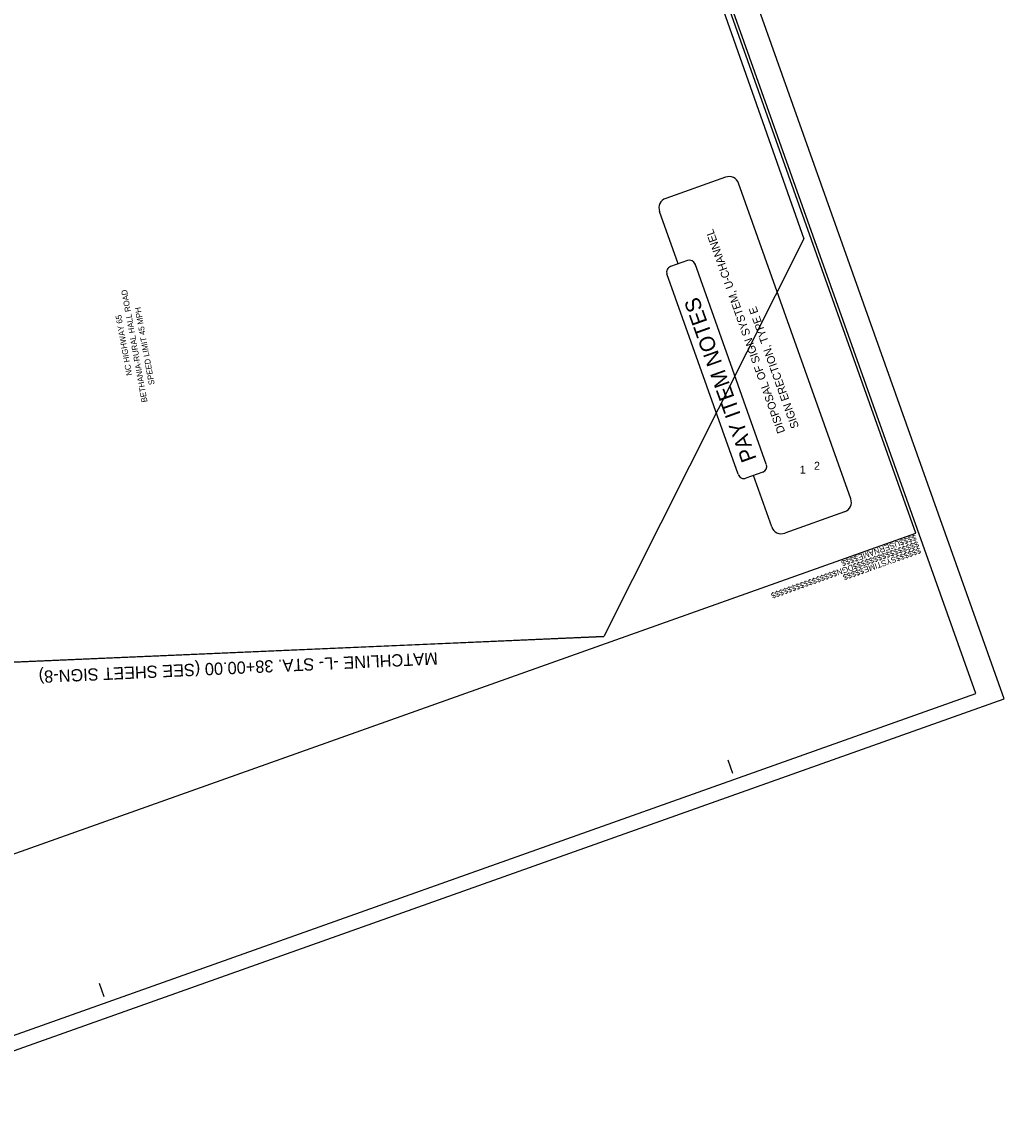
# Model space of a CAD drawing. Extents: x 1615843 to 1617444, y 901966 to 903921.
# Drawn here: x 1616560 to 1617444, y 901966 to 902943 of the extents above; entities that cross this region are included whole.
import ezdxf

# ---------------------------------------------------------------- set-up
doc = ezdxf.new("R2010")
doc.units = 0
for name, color, linetype in [('Default', 7, 'Continuous'), ('Old_Level_20', 7, 'Continuous'), ('Prop Conc 5in Monolithic Keyed In Island', 7, 'Continuous'), ('Prop Dimension Text', 7, 'Continuous'), ('Prop Lane Arrow CELL', 7, 'Continuous'), ('Prop PHM Concrete Structures Shape', 7, 'Continuous'), ('Prop Shade Medium', 7, 'Continuous'), ('Scratch_Level_2', 7, 'Continuous')]:
    doc.layers.add(name, color=color, linetype=linetype)

msp = doc.modelspace()

# ---------------------------------------------------------------- linework, layer by layer
at = {"layer": 'Old_Level_20'}
msp.add_lwpolyline([(1616920.55, 902382.99), (1616427.51, 902361.62), (1616381.79, 902566.75), (1616370.25, 902895), (1616376.63, 903177.08), (1616314.87, 903377.26), (1616220.94, 903360.1), (1616181.06, 903436.37), (1616369.18, 903520.6), (1616903.33, 903759.78), (1617120.19, 903154.34), (1617263.37, 902747.79), (1617083.45, 902390.05)], close=True, dxfattribs=at)
at = {"layer": 'Prop Conc 5in Monolithic Keyed In Island'}
for p, q in [((1617192.98, 902803.4), (1617139.07, 902784.24)), ((1617305.53, 902513.93), (1617204.58, 902797.88)), ((1617150.32, 902725.46), (1617133.55, 902772.63)), ((1617158.6, 902728.41), (1617143.51, 902723.04)), ((1617226.32, 902537.93), (1617211.22, 902532.56)), ((1617234.5, 902488.68), (1617218.04, 902534.98)), ((1617300.01, 902502.32), (1617246.11, 902483.16))]:
    msp.add_line(p, q, dxfattribs=at)
for points in [[(1617204.11, 902536.3), (1617140.04, 902716.51)], [(1617229.48, 902545.32), (1617165.42, 902725.53)]]:
    msp.add_lwpolyline(points, dxfattribs=at)
for centre, radius, start, end in [((1617196.02, 902794.84), 9.09, 19.57069, 109.57069), ((1617142.11, 902775.67), 9.09, 109.57069, 199.57069), ((1617160.43, 902723.27), 5.45, 19.57069, 109.57069), ((1617145.33, 902717.9), 5.45, 109.57069, 199.57069), ((1617224.5, 902543.06), 5.45, 289.57069, 19.57069), ((1617209.4, 902537.7), 5.45, 199.57069, 289.57069), ((1617296.97, 902510.89), 9.09, 289.57069, 19.57069), ((1617243.06, 902491.72), 9.09, 199.57069, 289.57069)]:
    msp.add_arc(centre, radius, start, end, dxfattribs=at)
at = {"layer": 'Prop Dimension Text'}
msp.add_line((1616299.46, 902356.07), (1617083.45, 902390.05), dxfattribs=at)
at = {"layer": 'Prop PHM Concrete Structures Shape'}
for p, q in [((1617199.45, 902266.98), (1617195.26, 902278.76)), ((1616634.11, 902066), (1616629.93, 902077.78))]:
    msp.add_line(p, q, dxfattribs=at)
msp.add_lwpolyline([(1615872.27, 903544.74), (1616374.72, 902131.39), (1617364.06, 902483.11), (1616861.61, 903896.45)], close=True, dxfattribs=at)
at = {"layer": 'Prop Shade Medium'}
msp.add_lwpolyline([(1615843.02, 903552.38), (1616407.11, 901965.67), (1617443.56, 902334.13), (1616879.47, 903920.85)], close=True, dxfattribs=at)
at = {"layer": 'Scratch_Level_2'}
msp.add_lwpolyline([(1615865.68, 903555.66), (1616423.91, 901985.43), (1617418.05, 902338.86), (1616859.83, 903909.09)], close=True, dxfattribs=at)

# ---------------------------------------------------------------- texts
at = {"layer": 'Default'}
for s, height, rotation, p in [('DISPOSAL OF SIGN SYSTEM, U-CHANNEL', 7.1994, 109.57069, (1617246.59, 902574.39)), ('BETHANIA-RURAL HALL ROAD ', 5.25, 100.40263, (1616673.03, 902601.29)), ('PAY ITEM NOTES', 13.8661, 109.75293, (1617220.98, 902550.03)), ('SIGN ERECTION, TYPE E', 7.1994, 109.57069, (1617259.04, 902578.82)), ('NC HIGHWAY 65', 5.25, 100.40263, (1616659.28, 902625.35)), ('SPEED LIMIT 45 MPH', 5.25, 100.40263, (1616679.48, 902616.99)), ('1', 7.2, 359.97341, (1617259.64, 902536.62)), ('2', 7.2, 359.97341, (1617272.41, 902540.13))]:
    msp.add_text(s, height=height, rotation=rotation, dxfattribs=at).set_placement(p)
at = {"layer": 'Prop Lane Arrow CELL'}
msp.add_text('MATCHLINE -L- STA. 38+00.00 (SEE SHEET SIGN-8)', height=11, rotation=182.66245, dxfattribs=at).set_placement((1616933.78, 902375.88))
at = {"layer": 'Prop PHM Concrete Structures Shape'}
for s, p in [('$$$$USERNAME$$$$', (1617363.45, 902481.99)), ('$$$$$$$$$$$$$$$$DGN$$$$$$$$$$$$$$$$', (1617365.66, 902476.09)), ('$$$$$$SYSTIME$$$$$', (1617367.5, 902470.32))]:
    msp.add_text(s, height=5.25, rotation=199.57069, dxfattribs=at).set_placement(p)

doc.saveas('drawing.dxf')
